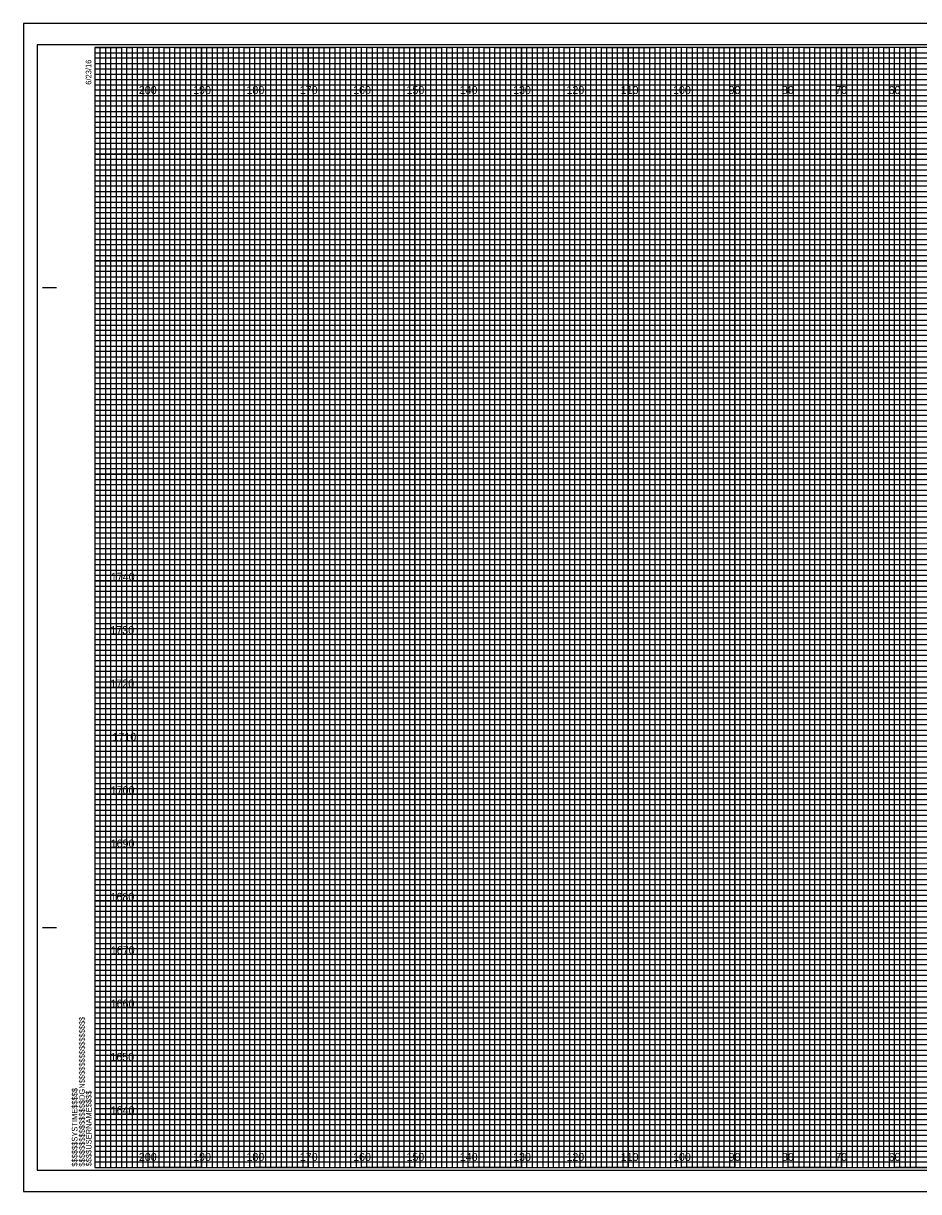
# Model space of a CAD drawing. Extents: x -3334 to 0, y 84 to 12624.
# Drawn here: x -711.6 to -543.7, y 524.2 to 743.2 of the extents above; entities that cross this region are included whole.
import ezdxf

# ---------------------------------------------------------------- set-up
doc = ezdxf.new("R2010")
doc.units = 0
for name, color, linetype in [('Old_Level_62', 7, 'Continuous'), ('Pattern 1', 7, 'Continuous'), ('Pattern 18', 7, 'Continuous'), ('Pattern 4', 7, 'Continuous'), ('Pattern 5', 7, 'Continuous'), ('Prop Dimension', 7, 'Continuous'), ('Prop Horizontal Alignment', 7, 'Continuous'), ('Raster_Level_0', 7, 'Continuous'), ('Scratch_Level_0', 7, 'Continuous'), ('Scratch_Level_3', 7, 'Continuous'), ('Scratch_Level_5', 7, 'Continuous')]:
    doc.layers.add(name, color=color, linetype=linetype)

msp = doc.modelspace()

# ---------------------------------------------------------------- linework, layer by layer
at = {"layer": 'Old_Level_62'}
for p, q in [((-708.04, 693.74), (-705.54, 693.74)), ((-707.94, 693.74), (-705.44, 693.74)), ((-708.04, 573.74), (-705.54, 573.74)), ((-707.94, 573.74), (-705.44, 573.74)), ((-698.24, 528.74), (-698.24, 528.74)), ((-698.24, 528.74), (-698.24, 528.74)), ((-698.24, 528.74), (-698.24, 528.74)), ((-698.24, 528.74), (-698.24, 528.74)), ((-698.24, 528.74), (-698.24, 528.74)), ((-698.24, 528.74), (-698.24, 528.74)), ((-698.24, 528.74), (-698.24, 528.74))]:
    msp.add_line(p, q, dxfattribs=at)
msp.add_lwpolyline([(-378.24, 738.74), (-698.24, 738.74), (-698.24, 528.74), (-378.24, 528.74)], close=True, dxfattribs=at)
at = {"layer": 'Pattern 18'}
msp.add_lwpolyline([(-711.64, 524.24), (-374.94, 524.24), (-374.94, 743.24), (-711.64, 743.24)], close=True, dxfattribs=at)
at = {"layer": 'Pattern 4'}
for p, q in [((-698.24, 737.74), (-438.24, 737.74)), ((-438.24, 736.72), (-698.24, 736.72)), ((-698.24, 736.72), (-698.24, 735.74)), ((-698.24, 735.74), (-438.24, 735.74)), ((-438.24, 734.63), (-698.24, 734.63)), ((-698.24, 734.63), (-698.24, 732.74)), ((-698.24, 732.74), (-378.24, 732.74))]:
    msp.add_line(p, q, dxfattribs=at)
for points in [[(-698.24, 731.74), (-428.24, 731.74), (-378.24, 731.74), (-378.24, 730.74), (-698.24, 730.74)], [(-698.24, 729.74), (-378.24, 729.74), (-378.24, 727.74), (-698.24, 727.74)], [(-698.24, 726.74), (-378.24, 726.74), (-378.24, 725.74), (-698.24, 725.72)], [(-698.24, 724.74), (-378.24, 724.74), (-378.24, 722.74), (-698.24, 722.74)], [(-698.24, 721.74), (-378.24, 721.74), (-378.24, 720.74), (-698.24, 720.74)], [(-698.24, 719.74), (-378.24, 719.74), (-378.24, 717.74), (-698.24, 717.74)], [(-698.24, 716.74), (-378.24, 716.74), (-378.24, 715.74), (-698.24, 715.74)], [(-698.24, 714.74), (-378.24, 714.74), (-378.24, 712.74), (-698.24, 712.74)], [(-698.24, 711.74), (-378.24, 711.74), (-378.24, 710.74), (-698.24, 710.74)], [(-698.24, 709.74), (-378.24, 709.74), (-378.24, 707.74), (-698.24, 707.74)], [(-698.24, 706.74), (-378.24, 706.74), (-378.24, 705.74), (-698.24, 705.74)], [(-698.24, 704.74), (-378.24, 704.74), (-378.24, 702.69), (-378.24, 701.74), (-378.24, 700.74), (-698.24, 700.74)], [(-698.24, 702.74), (-378.24, 702.74), (-378.24, 701.74), (-698.24, 701.74)], [(-698.24, 699.74), (-378.24, 699.74), (-378.24, 697.74), (-698.24, 697.77)], [(-698.24, 697.77), (-378.24, 697.74), (-378.24, 696.74), (-698.24, 696.74)], [(-698.24, 695.74), (-378.24, 695.74), (-378.24, 694.74), (-698.24, 694.74)], [(-698.24, 692.74), (-378.24, 692.74), (-378.24, 691.74), (-698.24, 691.74)], [(-698.24, 690.74), (-378.24, 690.74), (-378.24, 689.74), (-698.24, 689.74)], [(-698.31, 687.63), (-378.24, 687.63), (-378.24, 686.62), (-698.31, 686.62)], [(-698.24, 685.74), (-378.24, 685.74), (-378.24, 684.74), (-698.24, 684.74)], [(-698.24, 682.74), (-378.24, 682.74), (-378.24, 681.74), (-698.24, 681.74)], [(-698.24, 680.74), (-378.24, 680.74), (-378.24, 679.74), (-698.24, 679.74)], [(-698.24, 677.74), (-378.24, 677.74), (-378.24, 676.74), (-698.24, 676.74)], [(-698.24, 675.74), (-378.24, 675.74), (-378.24, 674.74), (-698.24, 674.74)], [(-698.24, 672.74), (-378.24, 672.74), (-378.24, 671.74), (-698.24, 671.74)], [(-698.24, 670.74), (-378.24, 670.74), (-378.24, 669.74), (-698.24, 669.74)], [(-698.24, 667.74), (-378.24, 667.74), (-378.25, 666.72), (-698.24, 666.74)], [(-698.24, 665.74), (-378.24, 665.74), (-378.24, 664.74), (-698.24, 664.74)], [(-698.24, 662.74), (-378.24, 662.74), (-378.24, 661.74), (-698.24, 661.74)], [(-698.24, 660.74), (-378.24, 660.74), (-378.24, 659.74), (-698.24, 659.74)], [(-698.24, 657.74), (-378.24, 657.74), (-378.24, 656.74), (-698.24, 656.74)], [(-698.24, 655.74), (-378.24, 655.74), (-378.24, 654.74), (-698.24, 654.74)], [(-698.24, 652.74), (-378.24, 652.74), (-378.24, 651.74), (-698.24, 651.74)], [(-698.24, 650.74), (-378.24, 650.74), (-378.24, 649.74), (-698.24, 649.74)], [(-698.24, 647.74), (-378.24, 647.74), (-378.24, 646.74), (-698.24, 646.74)], [(-698.24, 645.73), (-378.17, 645.65), (-378.24, 644.74), (-698.24, 644.74)], [(-698.24, 642.74), (-378.24, 642.74), (-378.24, 641.74), (-698.24, 641.74)], [(-698.24, 640.74), (-378.24, 640.74), (-378.24, 639.74), (-698.24, 639.74)], [(-698.24, 637.74), (-378.24, 637.74), (-378.24, 636.74), (-698.24, 636.74)], [(-698.24, 635.74), (-378.24, 635.74), (-378.24, 634.74), (-698.24, 634.74)], [(-698.24, 632.74), (-378.24, 632.74), (-378.24, 631.74), (-698.24, 631.74)], [(-698.24, 630.74), (-378.24, 630.74), (-378.24, 629.74), (-698.24, 629.74)], [(-698.24, 627.74), (-378.24, 627.74), (-378.24, 626.74), (-698.24, 626.74)], [(-698.24, 625.74), (-378.24, 625.74), (-378.24, 624.74), (-698.24, 624.74)], [(-698.24, 622.74), (-378.24, 622.74), (-378.24, 621.74), (-698.24, 621.74)], [(-698.24, 620.74), (-378.24, 620.74), (-378.24, 619.74), (-698.24, 619.74)], [(-698.24, 617.74), (-378.24, 617.74), (-378.24, 616.74), (-698.24, 616.74)], [(-698.24, 615.74), (-378.24, 615.74), (-378.24, 614.74), (-698.24, 614.74)], [(-698.24, 612.74), (-378.24, 612.74), (-378.24, 611.74), (-698.24, 611.74)], [(-698.24, 610.74), (-378.24, 610.74), (-378.24, 609.74), (-698.24, 609.74)], [(-698.24, 607.74), (-378.24, 607.74), (-378.25, 606.72), (-698.24, 606.74)], [(-698.24, 605.74), (-378.24, 605.74), (-378.24, 604.74), (-698.24, 604.74)], [(-698.24, 602.74), (-378.24, 602.74), (-378.24, 601.74), (-698.24, 601.74)], [(-698.24, 600.74), (-378.24, 600.74), (-378.24, 599.74), (-698.24, 599.74)], [(-698.24, 597.74), (-378.24, 597.74), (-378.24, 596.74), (-698.24, 596.74)], [(-698.24, 595.74), (-378.24, 595.74), (-378.24, 594.74), (-698.24, 594.74)], [(-698.24, 592.74), (-378.24, 592.74), (-378.24, 591.74), (-698.24, 591.74)], [(-698.24, 590.74), (-378.24, 590.74), (-378.24, 589.74), (-698.24, 589.74)], [(-698.24, 587.74), (-378.24, 587.74), (-378.24, 586.74), (-698.24, 586.74)], [(-698.24, 585.73), (-378.17, 585.65), (-378.24, 584.74), (-698.24, 584.74)], [(-698.24, 582.74), (-378.24, 582.74), (-378.24, 581.74), (-698.24, 581.74)], [(-698.24, 580.74), (-378.24, 580.74), (-378.24, 579.74), (-698.24, 579.74)], [(-698.24, 577.74), (-378.24, 577.74), (-378.24, 576.74), (-698.24, 576.74)], [(-698.24, 575.74), (-378.24, 575.74), (-378.24, 574.74), (-698.24, 574.74)], [(-698.24, 572.74), (-378.24, 572.74), (-378.24, 571.74), (-698.24, 571.74)], [(-698.24, 570.74), (-378.24, 570.74), (-378.24, 569.74), (-698.24, 569.74)], [(-698.24, 567.74), (-378.24, 567.74), (-378.24, 566.74), (-698.24, 566.74)], [(-698.24, 565.74), (-378.24, 565.74), (-378.24, 564.74), (-698.24, 564.74)], [(-698.24, 562.74), (-378.24, 562.74), (-378.24, 561.74), (-698.24, 561.74)], [(-698.24, 560.74), (-378.24, 560.74), (-378.24, 559.74), (-698.24, 559.74)], [(-698.24, 557.74), (-378.24, 557.74), (-378.24, 556.74), (-698.24, 556.74)], [(-698.24, 555.74), (-378.24, 555.74), (-378.24, 554.74), (-698.24, 554.74)], [(-698.24, 552.74), (-378.24, 552.74), (-378.24, 551.74), (-698.24, 551.74)], [(-698.24, 550.74), (-378.24, 550.74), (-378.24, 549.74), (-698.24, 549.74)], [(-698.24, 547.74), (-378.24, 547.74), (-378.24, 546.74), (-698.24, 546.74)], [(-698.24, 545.74), (-378.24, 545.74), (-378.24, 544.74), (-698.24, 544.74)], [(-698.24, 542.74), (-378.24, 542.74), (-378.24, 541.74), (-698.24, 541.74)], [(-698.24, 540.74), (-378.24, 540.74), (-378.24, 539.74), (-698.24, 539.74)], [(-698.24, 537.74), (-378.24, 537.74), (-378.24, 536.74), (-698.24, 536.74)], [(-698.24, 535.74), (-378.24, 535.74), (-378.24, 534.74), (-698.24, 534.74)], [(-698.24, 532.74), (-378.24, 532.74), (-378.24, 531.74), (-698.24, 531.74)], [(-698.24, 530.74), (-378.24, 530.74), (-378.24, 529.74), (-698.24, 529.74)]]:
    msp.add_lwpolyline(points, dxfattribs=at)
at = {"layer": 'Pattern 5'}
for p, q in [((-374.94, 743.24), (-711.64, 743.24)), ((-711.64, 743.24), (-711.64, 524.24)), ((-711.64, 524.24), (-374.94, 524.24))]:
    msp.add_line(p, q, dxfattribs=at)
at = {"layer": 'Prop Dimension'}
for points in [[(-698.24, 528.74), (-697.24, 528.74), (-697.24, 738.74), (-696.24, 738.74), (-696.24, 528.74)], [(-696.24, 528.74), (-695.24, 528.74), (-695.24, 738.74), (-694.24, 738.74), (-694.24, 528.74)], [(-693.24, 528.74), (-692.24, 528.74), (-692.24, 738.74), (-691.24, 738.74), (-691.24, 528.74)], [(-691.24, 528.74), (-690.24, 528.74), (-690.24, 738.74), (-689.24, 738.74), (-689.24, 528.74)], [(-688.24, 528.74), (-687.24, 528.74), (-687.24, 738.74), (-686.24, 738.74), (-686.24, 528.74)], [(-686.24, 528.74), (-685.24, 528.74), (-685.24, 738.74), (-684.24, 738.74), (-684.24, 528.74)], [(-683.24, 528.74), (-682.24, 528.74), (-682.24, 738.74), (-681.24, 738.74), (-681.24, 528.74)], [(-681.24, 528.74), (-680.24, 528.74), (-680.24, 738.74), (-679.24, 738.74), (-679.24, 528.74)], [(-678.24, 528.74), (-677.24, 528.74), (-677.24, 738.74), (-676.24, 738.74), (-676.24, 528.74)], [(-676.24, 528.74), (-675.24, 528.74), (-675.24, 738.74), (-674.24, 738.74), (-674.24, 528.74)], [(-673.24, 528.74), (-672.24, 528.74), (-672.24, 738.74), (-671.24, 738.74), (-671.24, 528.74)], [(-671.24, 528.74), (-670.24, 528.74), (-670.24, 738.74), (-669.24, 738.74), (-669.24, 528.74)], [(-668.24, 528.74), (-667.24, 528.74), (-667.24, 738.74), (-666.24, 738.74), (-666.24, 528.74)], [(-666.24, 528.74), (-665.24, 528.74), (-665.24, 738.74), (-664.24, 738.74), (-664.24, 528.74)], [(-663.24, 528.74), (-662.24, 528.74), (-662.24, 738.74), (-661.24, 738.74), (-661.24, 528.74)], [(-661.24, 528.74), (-660.24, 528.74), (-660.24, 738.74), (-659.24, 738.74), (-659.24, 528.74)], [(-658.24, 528.74), (-657.24, 528.74), (-657.24, 738.74), (-656.24, 738.74), (-656.24, 528.74)], [(-656.24, 528.74), (-655.24, 528.74), (-655.24, 738.74), (-654.24, 738.74), (-654.24, 528.74)], [(-653.24, 528.74), (-652.24, 528.74), (-652.24, 738.74), (-651.24, 738.74), (-651.24, 528.74)], [(-651.24, 528.74), (-650.24, 528.74), (-650.24, 738.74), (-649.24, 738.74), (-649.24, 528.74)], [(-648.24, 528.74), (-647.24, 528.74), (-647.24, 738.74), (-646.24, 738.74), (-646.24, 528.74)], [(-646.24, 528.74), (-645.24, 528.74), (-645.24, 738.74), (-644.24, 738.74), (-644.24, 528.74)], [(-643.24, 528.74), (-642.24, 528.74), (-642.24, 738.74), (-641.24, 738.74), (-641.24, 528.74)], [(-641.24, 528.74), (-640.24, 528.74), (-640.24, 738.74), (-639.24, 738.74), (-639.24, 528.74)], [(-638.24, 528.74), (-637.24, 528.74), (-637.24, 738.74), (-636.24, 738.74), (-636.24, 528.74)], [(-636.24, 528.74), (-635.24, 528.74), (-635.24, 738.74), (-634.24, 738.74), (-634.24, 528.74)], [(-633.24, 528.74), (-632.24, 528.74), (-632.24, 738.74), (-631.24, 738.74), (-631.24, 528.74)], [(-631.24, 528.74), (-630.24, 528.74), (-630.24, 738.74), (-629.24, 738.74), (-629.24, 528.74)], [(-628.24, 528.74), (-627.24, 528.74), (-627.24, 738.74), (-626.24, 738.74), (-626.24, 528.74)], [(-626.24, 528.74), (-625.24, 528.74), (-625.24, 738.74), (-624.24, 738.74), (-624.24, 528.74)], [(-623.24, 528.74), (-622.24, 528.74), (-622.24, 738.74), (-621.24, 738.74), (-621.24, 528.74)], [(-621.24, 528.74), (-620.24, 528.74), (-620.24, 738.74), (-619.24, 738.74), (-619.24, 528.74)], [(-618.24, 528.74), (-617.24, 528.74), (-617.24, 738.74), (-616.24, 738.74), (-616.24, 528.74)], [(-616.24, 528.74), (-615.24, 528.74), (-615.24, 738.74), (-614.24, 738.74), (-614.24, 528.74)], [(-613.24, 528.74), (-612.24, 528.74), (-612.24, 738.74), (-611.24, 738.74), (-611.24, 528.74)], [(-611.24, 528.74), (-610.24, 528.74), (-610.24, 738.74), (-609.24, 738.74), (-609.24, 528.74)], [(-608.24, 528.74), (-607.24, 528.74), (-607.24, 738.74), (-606.24, 738.74), (-606.24, 528.74)], [(-606.24, 528.74), (-605.24, 528.74), (-605.24, 738.74), (-604.24, 738.74), (-604.24, 528.74)], [(-603.24, 528.74), (-602.24, 528.74), (-602.24, 738.74), (-601.24, 738.74), (-601.24, 528.74)], [(-601.24, 528.74), (-600.24, 528.74), (-600.24, 738.74), (-599.24, 738.74), (-599.24, 528.74)], [(-598.24, 528.74), (-597.24, 528.74), (-597.24, 738.74), (-596.24, 738.74), (-596.24, 528.74)], [(-596.24, 528.74), (-595.24, 528.74), (-595.24, 738.74), (-594.24, 738.74), (-594.24, 528.74)], [(-593.24, 528.74), (-592.24, 528.74), (-592.24, 738.74), (-591.24, 738.74), (-591.24, 528.74)], [(-591.24, 528.74), (-590.24, 528.74), (-590.24, 738.74), (-589.24, 738.74), (-589.24, 528.74)], [(-588.24, 528.74), (-587.24, 528.74), (-587.24, 738.74), (-586.24, 738.74), (-586.24, 528.74)], [(-586.24, 528.74), (-585.24, 528.74), (-585.24, 738.74), (-584.24, 738.74), (-584.24, 528.74)], [(-583.24, 528.74), (-582.24, 528.74), (-582.24, 738.74), (-581.24, 738.74), (-581.24, 528.74)], [(-581.24, 528.74), (-580.24, 528.74), (-580.24, 738.74), (-579.24, 738.74), (-579.24, 528.74)], [(-578.24, 528.74), (-577.24, 528.74), (-577.24, 738.74), (-576.24, 738.74), (-576.24, 528.74)], [(-576.24, 528.74), (-575.24, 528.74), (-575.24, 738.74), (-574.24, 738.74), (-574.24, 528.74)], [(-573.24, 528.74), (-572.24, 528.74), (-572.24, 738.74), (-571.24, 738.74), (-571.24, 528.74)], [(-571.24, 528.74), (-570.24, 528.74), (-570.24, 738.74), (-569.24, 738.74), (-569.24, 528.74)], [(-568.24, 528.74), (-567.24, 528.74), (-567.24, 738.74), (-566.24, 738.74), (-566.24, 528.74)], [(-566.24, 528.74), (-565.24, 528.74), (-565.24, 738.74), (-564.24, 738.74), (-564.24, 528.74)], [(-563.24, 528.74), (-562.24, 528.74), (-562.24, 738.74), (-561.24, 738.74), (-561.24, 528.74)], [(-561.24, 528.74), (-560.24, 528.74), (-560.24, 738.74), (-559.24, 738.74), (-559.24, 528.74)], [(-558.24, 528.74), (-557.24, 528.74), (-557.24, 738.74), (-556.24, 738.74), (-556.24, 528.74)], [(-556.24, 528.74), (-555.24, 528.74), (-555.24, 738.74), (-554.24, 738.74), (-554.24, 528.74)], [(-553.24, 528.74), (-552.24, 528.74), (-552.24, 738.74), (-551.24, 738.74), (-551.24, 528.74)], [(-551.24, 528.74), (-550.24, 528.74), (-550.24, 738.74), (-549.24, 738.74), (-549.24, 528.74)], [(-548.24, 528.74), (-547.24, 528.74), (-547.24, 738.74), (-546.24, 738.74), (-546.24, 528.74)], [(-546.24, 528.74), (-545.24, 528.74), (-545.24, 738.74), (-544.24, 738.74), (-544.24, 528.74)]]:
    msp.add_lwpolyline(points, dxfattribs=at)
at = {"layer": 'Prop Horizontal Alignment'}
for points in [[(-698.24, 738.74), (-693.24, 738.74), (-693.24, 528.74), (-683.24, 528.74), (-683.24, 738.74), (-673.24, 738.74), (-673.24, 528.74), (-663.24, 528.74), (-663.24, 738.74), (-653.24, 738.74), (-653.24, 528.74), (-643.24, 528.74), (-643.24, 738.74), (-633.24, 738.74), (-633.24, 528.74), (-623.24, 528.74), (-623.24, 738.74), (-613.24, 738.74), (-613.24, 528.74), (-603.24, 528.74), (-603.24, 738.74), (-593.24, 738.74), (-593.24, 528.74), (-583.24, 528.74), (-583.24, 738.74), (-573.24, 738.74), (-573.24, 528.74), (-563.24, 528.74), (-563.24, 738.74), (-553.24, 738.74), (-553.24, 528.74), (-543.24, 528.74)], [(-698.24, 733.74), (-423.24, 733.74)], [(-698.24, 713.74), (-378.24, 713.74), (-378.24, 723.74), (-698.24, 723.74)], [(-698.24, 693.74), (-378.24, 693.74), (-378.24, 703.74), (-698.24, 703.74)], [(-698.24, 673.74), (-378.24, 673.74), (-378.24, 683.74), (-698.24, 683.74)], [(-698.24, 653.74), (-378.24, 653.74), (-378.24, 663.74), (-698.24, 663.74)], [(-698.24, 633.74), (-378.24, 633.74), (-378.24, 643.74), (-698.24, 643.74)], [(-698.24, 613.74), (-378.24, 613.74), (-378.24, 623.74), (-698.24, 623.74)], [(-698.24, 593.74), (-378.24, 593.74), (-378.24, 603.74), (-698.24, 603.74)], [(-698.24, 573.74), (-378.24, 573.74), (-378.24, 583.74), (-698.24, 583.74)], [(-698.24, 553.74), (-378.24, 553.74), (-378.24, 563.74), (-698.24, 563.74)], [(-698.24, 533.74), (-378.24, 533.74), (-378.24, 543.74), (-698.24, 543.74)]]:
    msp.add_lwpolyline(points, dxfattribs=at)
at = {"layer": 'Scratch_Level_0'}
for p, q in [((-688.24, 528.74), (-688.24, 738.74)), ((-678.24, 528.74), (-678.24, 738.74)), ((-668.24, 528.74), (-668.24, 738.74)), ((-658.24, 528.74), (-658.24, 738.74)), ((-648.24, 528.74), (-648.24, 738.74)), ((-638.24, 528.74), (-638.24, 738.74)), ((-628.24, 528.74), (-628.24, 738.74)), ((-618.24, 528.74), (-618.24, 738.74)), ((-608.24, 528.74), (-608.24, 738.74)), ((-598.24, 528.74), (-598.24, 738.74)), ((-588.24, 528.74), (-588.24, 738.74)), ((-578.24, 528.74), (-578.24, 738.74)), ((-568.24, 528.74), (-568.24, 738.74)), ((-558.24, 528.74), (-558.24, 738.74)), ((-548.24, 528.74), (-548.24, 738.74)), ((-698.24, 728.74), (-378.24, 728.74)), ((-698.24, 718.74), (-378.24, 718.74)), ((-698.24, 708.74), (-378.24, 708.74)), ((-698.24, 698.74), (-378.24, 698.74)), ((-698.24, 688.74), (-378.24, 688.74)), ((-698.24, 678.74), (-378.24, 678.74)), ((-698.24, 668.74), (-378.24, 668.74)), ((-698.24, 658.74), (-378.24, 658.74)), ((-698.24, 648.74), (-378.24, 648.74)), ((-698.24, 638.74), (-378.24, 638.74)), ((-698.24, 628.74), (-378.24, 628.74)), ((-698.24, 618.74), (-378.24, 618.74)), ((-698.24, 608.74), (-378.24, 608.74)), ((-698.24, 598.74), (-378.24, 598.74)), ((-698.24, 588.74), (-378.24, 588.74)), ((-698.24, 578.74), (-378.24, 578.74)), ((-698.24, 568.74), (-378.24, 568.74)), ((-698.24, 558.74), (-378.24, 558.74)), ((-698.24, 548.74), (-378.24, 548.74)), ((-698.24, 538.74), (-378.24, 538.74))]:
    msp.add_line(p, q, dxfattribs=at)
at = {"layer": 'Scratch_Level_3'}
for p, q in [((-688.24, 738.74), (-698.24, 738.74)), ((-688.24, 528.74), (-688.24, 738.74)), ((-668.24, 738.74), (-678.24, 738.74)), ((-678.24, 738.74), (-678.24, 528.74)), ((-668.24, 528.74), (-668.24, 738.74)), ((-648.24, 738.74), (-658.24, 738.74)), ((-658.24, 738.74), (-658.24, 528.74)), ((-648.24, 528.74), (-648.24, 738.74)), ((-628.24, 738.74), (-638.24, 738.74)), ((-638.24, 738.74), (-638.24, 528.74)), ((-628.24, 528.74), (-628.24, 738.74)), ((-608.24, 738.74), (-618.24, 738.74)), ((-618.24, 738.74), (-618.24, 528.74)), ((-608.24, 528.74), (-608.24, 738.74)), ((-588.24, 738.74), (-598.24, 738.74)), ((-598.24, 738.74), (-598.24, 528.74)), ((-588.24, 528.74), (-588.24, 738.74)), ((-568.24, 738.74), (-578.24, 738.74)), ((-578.24, 738.74), (-578.24, 528.74)), ((-568.24, 528.74), (-568.24, 738.74)), ((-548.24, 738.74), (-558.24, 738.74)), ((-558.24, 738.74), (-558.24, 528.74)), ((-548.24, 528.74), (-548.24, 738.74)), ((-678.24, 528.74), (-688.24, 528.74)), ((-658.24, 528.74), (-668.24, 528.74)), ((-638.24, 528.74), (-648.24, 528.74)), ((-618.24, 528.74), (-628.24, 528.74)), ((-598.24, 528.74), (-608.24, 528.74)), ((-578.24, 528.74), (-588.24, 528.74)), ((-558.24, 528.74), (-568.24, 528.74)), ((-538.24, 528.74), (-548.24, 528.74))]:
    msp.add_line(p, q, dxfattribs=at)
for points in [[(-698.24, 728.74), (-378.24, 728.74), (-378.24, 718.74), (-698.24, 718.74)], [(-698.24, 708.74), (-378.24, 708.74), (-378.24, 698.74), (-698.24, 698.74)], [(-698.24, 688.74), (-378.24, 688.74), (-378.24, 678.74), (-698.24, 678.74)], [(-698.24, 668.74), (-378.24, 668.74), (-378.24, 658.74), (-698.24, 658.74)], [(-698.24, 648.74), (-378.24, 648.74), (-378.24, 638.74), (-698.24, 638.74)], [(-698.24, 628.74), (-378.24, 628.74), (-378.24, 618.74), (-698.24, 618.74)], [(-698.24, 608.74), (-378.24, 608.74), (-378.24, 598.74), (-698.24, 598.74)], [(-698.24, 588.74), (-378.24, 588.74), (-378.24, 578.74), (-698.24, 578.74)], [(-698.24, 568.74), (-378.24, 568.74), (-378.24, 558.74), (-698.24, 558.74)], [(-698.24, 548.74), (-378.24, 548.74), (-378.24, 538.74), (-698.24, 538.74)]]:
    msp.add_lwpolyline(points, dxfattribs=at)
at = {"layer": 'Scratch_Level_5'}
msp.add_lwpolyline([(-709.04, 528.24), (-375.84, 528.24), (-375.84, 739.24), (-709.04, 739.24)], close=True, dxfattribs=at)

# ---------------------------------------------------------------- texts
at = {"layer": 'Old_Level_62'}
for s, p in [('6/23/16', (-698.89, 731.74)), ('$$$$$$$$$$$$$$$$DGN$$$$$$$$$$$$$$$$', (-700.12, 528.92)), ('$$$$$$SYSTIME$$$$$', (-701.5, 528.92)), ('$$$$USERNAME$$$$', (-698.86, 528.97))]:
    msp.add_text(s, height=1.05, rotation=90, dxfattribs=at).set_placement(p)
at = {"layer": 'Pattern 1'}
for s, p in [('1740', (-695.24, 638.74)), ('1730', (-695.32, 628.74)), ('1720', (-695.31, 618.74)), ('1710', (-694.93, 608.74)), ('1700', (-695.26, 598.74)), ('1690', (-695.27, 588.74)), ('1680', (-695.3, 578.74)), ('1670', (-695.24, 568.74)), ('1660', (-695.27, 558.74)), ('1650', (-695.32, 548.74)), ('1640', (-695.27, 538.74))]:
    msp.add_text(s, height=1.5, dxfattribs=at).set_placement(p)
at = {"layer": 'Raster_Level_0'}
for s, p in [('200', (-689.98, 729.99)), ('190', (-679.8, 729.99)), ('180', (-669.8, 729.99)), ('170', (-659.8, 729.99)), ('160', (-649.8, 729.99)), ('150', (-639.8, 729.99)), ('140', (-629.8, 729.99)), ('130', (-619.8, 729.99)), ('120', (-609.8, 729.99)), ('110', (-599.62, 729.99)), ('100', (-589.8, 729.99)), ('90', (-579.38, 729.99)), ('80', (-569.38, 729.99)), ('70', (-559.38, 729.99)), ('60', (-549.38, 729.99)), ('200', (-689.98, 529.99)), ('190', (-679.8, 529.99)), ('180', (-669.8, 529.99)), ('170', (-659.8, 529.99)), ('160', (-649.8, 529.99)), ('150', (-639.8, 529.99)), ('140', (-629.8, 529.99)), ('130', (-619.8, 529.99)), ('120', (-609.8, 529.99)), ('110', (-599.62, 529.99)), ('100', (-589.8, 529.99)), ('90', (-579.38, 529.99)), ('80', (-569.38, 529.99)), ('70', (-559.38, 529.99)), ('60', (-549.38, 529.99))]:
    msp.add_text(s, height=1.5, dxfattribs=at).set_placement(p)

doc.saveas('drawing.dxf')
